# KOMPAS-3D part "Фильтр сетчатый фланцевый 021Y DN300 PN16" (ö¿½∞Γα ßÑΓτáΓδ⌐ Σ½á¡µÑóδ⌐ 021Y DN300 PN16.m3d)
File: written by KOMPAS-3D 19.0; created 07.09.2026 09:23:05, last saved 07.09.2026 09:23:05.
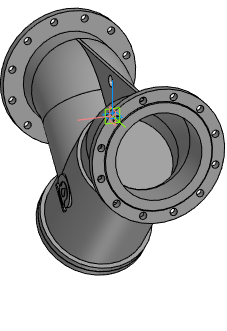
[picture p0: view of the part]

Document properties: Автор: Энергия; Полное имя файла: Z:\3.Личные\sachek\Dendor\_3D для проектировщиков\8.3 Фильтр сетчатый 021Y\021Y_STP\Фильтр сетчатый фланцевый 021Y DN300 PN16.m3d

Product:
- Part/product: Фильтр сетчатый фланцевый 021Y DN300 PN16

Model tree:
1. Операция без истории:1  (labels: Фильтр сетчатый фланцевый 021Y DN300 PN16)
